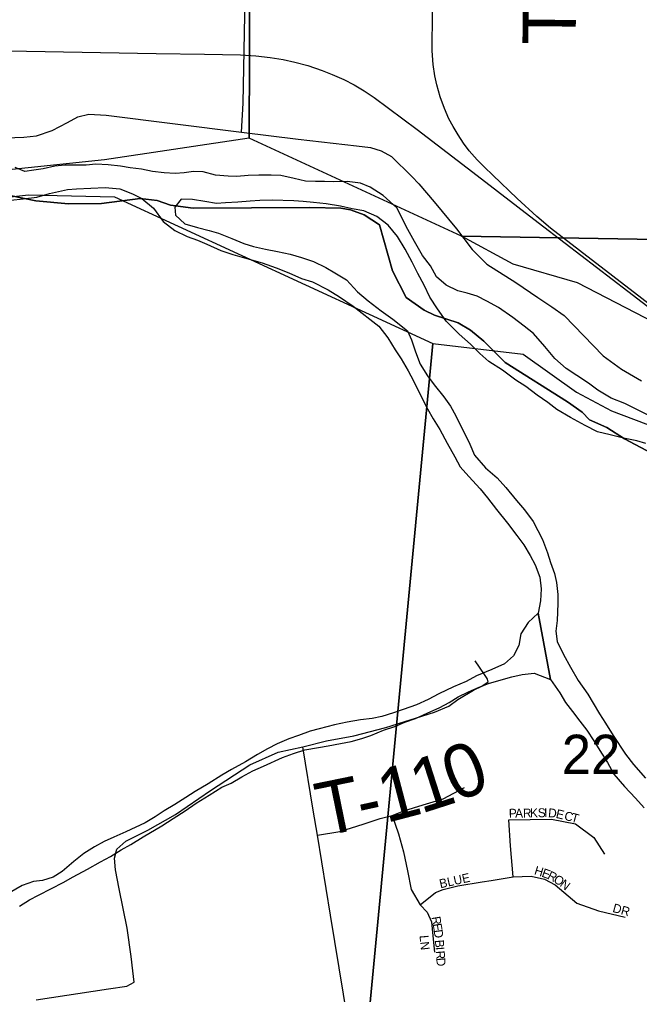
# Model space of a CAD drawing. Extents: x 1310247 to 1552180, y 377264 to 706493.
# Drawn here: x 1398339 to 1401822, y 525062 to 530538 of the extents above; entities that cross this region are included whole.
import ezdxf

# ---------------------------------------------------------------- set-up
doc = ezdxf.new("R2010")
doc.units = 0
for name, color, linetype in [('GM_X_County_Road', 7, 'Continuous'), ('GM_X_Major_River', 7, 'Continuous'), ('GM_X_Minor_River', 7, 'Continuous'), ('GM_X_Rail_Line', 7, 'Continuous'), ('GM_X_Rail_Line_Text', 7, 'Continuous'), ('GM_X_Section', 7, 'Continuous'), ('GM_X_Section_Text', 7, 'Continuous'), ('GM_X_Township', 7, 'Continuous'), ('GM_X_Township_Road', 7, 'Continuous'), ('GM_X_Township_Road_Text', 7, 'Continuous'), ('GM_X_Township_Subdivision', 7, 'Continuous'), ('GM_X_Township_Subdivision_Text', 7, 'Continuous')]:
    doc.layers.add(name, color=color, linetype=linetype)

msp = doc.modelspace()

# ---------------------------------------------------------------- linework, layer by layer
at = {"layer": 'GM_X_County_Road'}
for points in [[(1396748.8, 529601.3), (1396870.4, 529646.6), (1397025.7, 529692.9), (1397319.1, 529747), (1397411.7, 529763.5), (1397653.3, 529831.7), (1397792.9, 529848.2), (1398159.3, 529870.2), (1398362.5, 529877.2), (1398434.7, 529885.8), (1398523.3, 529914.1), (1398608.8, 529960.4), (1398666.1, 529992.5), (1398728.9, 530007.5), (1398825.4, 530000.4), (1399586.3, 529904.7)], [(1399586.3, 529904.7), (1399905, 529866), (1400232, 529828.6), (1400310.6, 529820.2), (1400371.1, 529800.4), (1400428.3, 529768.7), (1400543.8, 529656.9), (1400581.7, 529615.8), (1400668.8, 529513.5), (1400794.3, 529361.9), (1400882.5, 529247.1), (1400964.7, 529164.4), (1401127.6, 529062), (1401250.3, 528976.6), (1401330.1, 528924), (1401399.1, 528875.9), (1401618.7, 528649), (1401721.1, 528574.9), (1401834.2, 528509.3)], [(1398432.7, 525032.2), (1398838.6, 525093.1), (1398941.7, 525109.1), (1398983.9, 525130.9), (1398975.2, 525195), (1398966.4, 525275), (1398943.1, 525433.7), (1398898, 525655), (1398877.6, 525762.7), (1398873.3, 525828.2), (1398884.9, 525877.7), (1398935.9, 525922.8), (1399059.6, 525985.4), (1399215.4, 526072.8), (1399411.9, 526208.2), (1399633.2, 526350.8), (1399791.8, 526422.1), (1399931.6, 526452.7)], [(1400183.5, 524914.8), (1400086.4, 525507.7), (1400013.8, 525957.1), (1399988.2, 526097.8), (1399931.6, 526452.7)]]:
    msp.add_lwpolyline(points, dxfattribs=at)
at = {"layer": 'GM_X_Major_River'}
msp.add_line((1401252.3, 527204.4), (1401321.7, 526830.8), dxfattribs=at)
for points in [[(1399623, 529662.2), (1399560.7, 529656.2), (1399510.7, 529657.7), (1399440.9, 529663.9), (1399371.4, 529682.1), (1399317.4, 529683.8), (1399263.1, 529677.5), (1399212.9, 529673), (1399151, 529676.9), (1399085.2, 529685), (1399023.5, 529697), (1398959.7, 529705), (1398905.9, 529714.7), (1398836.1, 529722.8), (1398768.1, 529725), (1398713.9, 529720.6), (1398651.9, 529720.6), (1398593.8, 529720.4), (1398537.6, 529714.1), (1398471.1, 529700.1), (1398418.8, 529691.7), (1398368.5, 529685.3), (1398315.1, 529707)], [(1401904.9, 528299.3), (1401814.2, 528344.2), (1401739.3, 528380.7), (1401664.1, 528411.1), (1401587.4, 528455.6), (1401536.6, 528495.3), (1401469.9, 528539.5), (1401411.1, 528577.5), (1401346.7, 528633.6), (1401290.8, 528701.6), (1401227, 528773.8), (1401174.2, 528815.5), (1401111.6, 528863.6), (1401029.3, 528920.3), (1400964.4, 528956.5), (1400911.2, 528984.2), (1400853.7, 529002), (1400802, 529013.7), (1400736.9, 529045.8), (1400682.4, 529093.6), (1400648.2, 529154.9), (1400604, 529212.4), (1400558.4, 529292.1), (1400520.5, 529359.5), (1400458.1, 529479.8), (1400382.2, 529550.3), (1400309.6, 529596.7), (1400254.2, 529618.5), (1400180.5, 529628.8), (1400104.4, 529627.2), (1400052.4, 529628.8), (1400002.3, 529628.4), (1399946.3, 529630.1), (1399882.7, 529646.1), (1399807.2, 529662.5), (1399753.2, 529664.2), (1399683.1, 529664.4), (1399623, 529662.2)], [(1398289.4, 529523.2), (1398359.7, 529531.1), (1398436.1, 529540.8), (1398506.8, 529560.6), (1398557.2, 529573.1), (1398607.6, 529583.5), (1398659.8, 529587.9), (1398820.1, 529595), (1398902, 529586.4), (1398973.2, 529560.1), (1399026.4, 529532.4), (1399090.8, 529478.2), (1399146.5, 529404.3), (1399211, 529354.1), (1399280, 529319.9), (1399339.4, 529298), (1399390.8, 529276.3), (1399469.8, 529241.8), (1399537.1, 529217.6), (1399590.7, 529203.9), (1399701.9, 529172.3), (1399781.1, 529143.8), (1399852.3, 529115.5), (1399923.3, 529083.2), (1399984.8, 529065.2), (1400073.5, 529020.3), (1400136.3, 528980.3), (1400212.8, 528927.7), (1400357.4, 528814.9), (1400407.5, 528751.2), (1400449.4, 528683.7), (1400483.9, 528632.4), (1400521.8, 528565.1), (1400552.1, 528507.9), (1400591.7, 528428.5), (1400631.3, 528351), (1400663.6, 528295.9), (1400699.7, 528234.6), (1400741.4, 528159), (1400785.1, 528081.5), (1400815.4, 528026.4), (1400863.7, 527970.7), (1400927.7, 527902.5), (1400968.1, 527851.1), (1401018.1, 527785.4), (1401079.8, 527709.2), (1401133.7, 527639.3), (1401172.1, 527588), (1401208.3, 527526.7), (1401236.7, 527475.7), (1401262.6, 527406.7), (1401270.5, 527340.2), (1401266.4, 527272.2), (1401252.3, 527204.4)], [(1399246.5, 529529.5), (1399211, 529484.6)], [(1401858.4, 528156.3), (1401806.9, 528172), (1401733.2, 528186.3), (1401657.7, 528204.7), (1401586.2, 528223), (1401517.2, 528257.2), (1401434.5, 528301.9), (1401357.9, 528348.4), (1401307, 528386.1), (1401248.3, 528428.1), (1401183.7, 528476.2), (1401126.8, 528512.1), (1401052.4, 528568.6), (1400975.9, 528617.1), (1400925.2, 528662.8), (1400872.8, 528714.6), (1400808.5, 528770.8), (1400736.7, 528843.2), (1400686.8, 528913), (1400644.8, 528978.5), (1400612.8, 529045.7), (1400576.8, 529111), (1400544.8, 529176.2), (1400505, 529247.6), (1400463.1, 529319.1), (1400411.1, 529382.9), (1400346.5, 529431.1), (1400273.4, 529463.4), (1400207.7, 529475.5), (1400142.1, 529489.6), (1400062.4, 529502.1), (1399990.6, 529510.4), (1399932.8, 529516.2), (1399880.8, 529519.8), (1399758.8, 529523.6), (1399688.7, 529521.8), (1399634.5, 529517.4), (1399566.3, 529511.5), (1399496.1, 529507.7), (1399446, 529505.3), (1399380.2, 529515.3), (1399310.5, 529527.5), (1399246.5, 529529.5)], [(1399211, 529484.6), (1399215.7, 529440.2), (1399268.2, 529390.4), (1399339.7, 529370.2), (1399405.2, 529354.1), (1399456.8, 529338.4), (1399531.9, 529308), (1399599.1, 529279.8), (1399652.7, 529264.1), (1399720.2, 529248), (1399787.9, 529235.8), (1399859.5, 529219.6), (1399923, 529201.5), (1399990.4, 529179.4), (1400059.4, 529145.2), (1400110.5, 529115.5), (1400175.3, 529075.3), (1400237.3, 529009.2), (1400297.8, 528957.2), (1400370.2, 528902.8), (1400436.7, 528854.6), (1400518.8, 528789.8), (1400541.2, 528739), (1400563.2, 528672.1), (1400589.1, 528603.1), (1400631.1, 528537.6), (1400669.5, 528486.2), (1400723.5, 528418.4), (1400759.9, 528367.1), (1400790.2, 528312), (1400814.7, 528261.1), (1400844.9, 528204), (1400869.4, 528153), (1400895.5, 528092.1), (1400957.3, 528019.9), (1401023.6, 527963.7), (1401072, 527910), (1401131.8, 527836), (1401176.2, 527784.4), (1401224.2, 527718.8), (1401277.1, 527616.8), (1401304.8, 527541.7), (1401323.2, 527489), (1401345.3, 527426.2), (1401355.7, 527375.7), (1401363.6, 527309.2), (1401364, 527257.1), (1401359.1, 527163), (1401353.2, 527103), (1401359.4, 527044.6), (1401395.2, 526971.3), (1401435, 526899.9), (1401478.7, 526826.3), (1401532.4, 526748.4), (1401562.8, 526697.3), (1401597, 526638.1), (1401631.4, 526584.9), (1401675.3, 526517.3), (1401744.1, 526410.9), (1401788.3, 526353.4), (1401856, 526277.1)], [(1401321.7, 526830.8), (1401374.4, 526755.3), (1401406.8, 526702.2), (1401445.3, 526650.9), (1401487.6, 526597.4), (1401526.1, 526546.1), (1401566.3, 526486.7), (1401598.6, 526431.5), (1401642.5, 526363.9), (1401678.5, 526298.7), (1401738.4, 526230.6), (1401800.4, 526164.5), (1401848.8, 526110.8)]]:
    msp.add_lwpolyline(points, dxfattribs=at)
at = {"layer": 'GM_X_Minor_River'}
msp.add_line((1401321.7, 526830.8), (1401252.3, 527204.4), dxfattribs=at)
for points in [[(1401252.3, 527204.4), (1401196.6, 527152), (1401156.5, 527087.1), (1401144.5, 527021.2), (1401114.7, 526964), (1401063.2, 526919.5), (1400992.2, 526887.6), (1400907, 526852.2), (1400847.9, 526819.9), (1400776.9, 526790), (1400695.6, 526750.4), (1400634.6, 526718.2), (1400569.6, 526688.2), (1400494.7, 526662.4), (1400440.1, 526644.1), (1400375.4, 526624), (1400320.9, 526611.7), (1400254.6, 526603.8), (1400180.2, 526592), (1400109.6, 526576.2), (1400022.9, 526554.8), (1399972.4, 526540.3), (1399905.6, 526516.4), (1399853, 526497.9), (1399786, 526469.9), (1399733.1, 526441.5), (1399676, 526409.2), (1399608.7, 526369.2), (1399529.3, 526325.5), (1399476.2, 526293.1), (1399398.7, 526245.4), (1399325.2, 526201.5), (1399274.2, 526169), (1399210.8, 526128.9), (1399151.7, 526092.7), (1399100.6, 526060.2), (1399045.5, 526025.8), (1398935.8, 525975), (1398868.8, 525945), (1398814, 525920.7), (1398761, 525890.2), (1398699.8, 525854.1), (1398644.3, 525807.7), (1398578.5, 525751.6), (1398527.5, 525721.1), (1398468.8, 525702.8), (1398416.6, 525696.4), (1398353.8, 525674.3), (1398282.5, 525632.4)], [(1398338.2, 525558.5), (1398395.3, 525592.8), (1398446.2, 525619.3), (1398519.5, 525657.2), (1398584.6, 525691.2), (1398639.6, 525721.6), (1398721, 525765.2), (1398794.4, 525807), (1398849.4, 525837.4), (1398910.6, 525873.6), (1398963.6, 525904), (1399033, 525947.9), (1399139, 526008.8), (1399202.4, 526050.9), (1399269.8, 526093), (1399331.2, 526137.2), (1399404.7, 526181), (1399476.1, 526226.9), (1399528.9, 526249.3), (1399588, 526283.6), (1399649.2, 526317.8), (1399710, 526344), (1399815.6, 526392.8), (1399878.4, 526414.9), (1399941.1, 526435), (1400019.6, 526448.6), (1400074, 526459), (1400142.4, 526470.9), (1400202.8, 526483), (1400261.4, 526499.2), (1400312, 526515.7), (1400384.9, 526545.5), (1400447.7, 526567.6), (1400504.5, 526591.9), (1400563.2, 526612.2), (1400630.2, 526642.2), (1400701.3, 526674.1), (1400752.2, 526702.5), (1400803.2, 526733), (1400862.1, 526761.3), (1400921, 526787.5), (1400973.7, 526808), (1401032.3, 526826.2), (1401105, 526846), (1401163.4, 526858.2), (1401229.7, 526866.2), (1401321.7, 526830.8)]]:
    msp.add_lwpolyline(points, dxfattribs=at)
at = {"layer": 'GM_X_Rail_Line'}
for points in [[(1402475.1, 528462.4), (1402399.7, 528531), (1402348.3, 528576.5), (1401322.5, 529366.2), (1401245.8, 529431.9), (1401135.8, 529533.5), (1400998.2, 529664.8), (1400952, 529708.3), (1400909.6, 529750.6), (1400865.4, 529801.2), (1400832.9, 529843.9), (1400802.9, 529889.8), (1400774.8, 529937.7), (1400751.9, 529981.1), (1400726.2, 530038.5), (1400702, 530104.9), (1400683, 530170.6), (1400672.8, 530222.8), (1400663.7, 530285.6), (1400658.1, 530361.6), (1400660.5, 530799.7)], [(1398167.9, 530365.1), (1399106.4, 530347.5), (1399377.5, 530343.4), (1399581.2, 530339.1), (1399666.3, 530334.8), (1399747.5, 530325.9), (1399820.5, 530314.2), (1399885.4, 530299.1), (1399958.1, 530280), (1400039.7, 530252.8), (1400096.4, 530229.9), (1400161.3, 530200.8), (1400219.2, 530170.8), (1400274.7, 530137.8), (1400332.3, 530100.5), (1400572.4, 529920.6), (1400910.1, 529661.8), (1401253.2, 529398), (1401404.3, 529282.6)], [(1401404.3, 529282.6), (1401757.2, 529012.3), (1402475.1, 528462.4)]]:
    msp.add_lwpolyline(points, dxfattribs=at)
at = {"layer": 'GM_X_Section'}
for points in [[(1394300.1, 534734.1), (1399648.2, 534645.7), (1399629, 529871.9), (1398816.2, 529750.5), (1398188.7, 529684.9), (1397894.7, 529685.6), (1397607.8, 529646.2), (1397412.5, 529592.6), (1397227.7, 529556.8), (1397139.3, 529538.9), (1397165.6, 529376.3), (1394220.6, 529425.6)], [(1399648.2, 534645.7), (1404926.4, 534635.9), (1404882.7, 529252.8), (1400822.5, 529320.7), (1399629, 529871.9)], [(1394632.2, 524597.9), (1394515.4, 525784.6), (1394762, 526163), (1394942.5, 526530.9), (1394994.2, 526609.8), (1395048.2, 526782.5), (1395253.1, 527081.9), (1395499.4, 527446.2), (1395844.6, 528022.4), (1395961, 528301.7), (1396143.5, 528763.6), (1396402.2, 528967.7), (1396589.9, 529125.4), (1396689.5, 529197.1), (1397322, 529394.7), (1397692.4, 529500.2), (1397877.8, 529560), (1398019, 529524.7), (1398133.1, 529526.2), (1398389.7, 529554.3), (1398873.5, 529543.2), (1400660.7, 528718.3), (1400210.2, 523974.4)], [(1400822.5, 529320.7), (1404882.7, 529252.8), (1404855.5, 523981.3), (1404604.2, 524056.7), (1404321.4, 524164.5), (1403984.6, 524339.6), (1403701.7, 524595.6), (1403586.6, 524777.3), (1403248.5, 525035), (1403011.3, 525592.4), (1402982.5, 526259.1), (1403005, 526890.6), (1403014.9, 527676.4), (1402881, 528207.5), (1402531, 528465.5), (1401909.4, 528833.8), (1401474.5, 529059.7), (1401112.9, 529164)]]:
    msp.add_lwpolyline(points, close=True, dxfattribs=at)
msp.add_lwpolyline([(1400210.2, 523974.4), (1400660.7, 528718.3), (1401169.3, 528658.7), (1401468.5, 528445.9), (1401666, 528339.3), (1402066.6, 528188.1)], dxfattribs=at)
at = {"layer": 'GM_X_Township'}
for points in [[(1401889.4, 528102.9), (1401738.1, 528183.4), (1401639, 528246.8), (1401542.3, 528289.2), (1401500.3, 528333.4), (1401417.5, 528390.6), (1401067.3, 528612.1), (1400948.6, 528731.1), (1400872.8, 528793.4), (1400802.9, 528833.7), (1400671.2, 528877.3), (1400612.3, 528905.3), (1400510.6, 528976.6), (1400435.4, 529127.4), (1400362.2, 529385.5), (1400274.6, 529441), (1400199.2, 529469.5), (1400143.4, 529478.2), (1399969.4, 529483.1), (1399313.8, 529478.4), (1399186.7, 529495.5), (1399113.2, 529522), (1399017.1, 529532.4), (1398799.7, 529504.8), (1398613.9, 529502.6), (1398431.5, 529520.7), (1398210.1, 529564.9)], [(1398210.1, 529564.9), (1398431.5, 529520.7), (1398613.9, 529502.6), (1398799.7, 529504.8), (1399017.1, 529532.4), (1399113.2, 529522), (1399186.7, 529495.5), (1399313.8, 529478.4), (1399969.4, 529483.1), (1400143.4, 529478.2), (1400199.2, 529469.5), (1400274.6, 529441), (1400362.2, 529385.5), (1400435.4, 529127.4), (1400510.6, 528976.6), (1400612.3, 528905.3), (1400671.2, 528877.3), (1400802.9, 528833.7), (1400872.8, 528793.4), (1400948.6, 528731.1), (1401067.3, 528612.1), (1401417.5, 528390.6), (1401500.3, 528333.4), (1401542.3, 528289.2), (1401639, 528246.8), (1401738.1, 528183.4), (1401889.4, 528102.9)]]:
    msp.add_lwpolyline(points, dxfattribs=at)
at = {"layer": 'GM_X_Township_Road'}
for points in [[(1399586.3, 529904.7), (1399596.2, 530069.2), (1399641.2, 532441.6), (1399654.1, 533920.8), (1399653.8, 534123.5)], [(1399931.6, 526452.7), (1400063, 526486.2), (1400217.8, 526513.8), (1400397.5, 526561.6), (1400671.5, 526647.7), (1400750.2, 526680.7), (1400801.4, 526719.1), (1400890.3, 526771.6), (1400936.7, 526793.8), (1400972.4, 526817.4), (1400967, 526836.2), (1400950.8, 526858.4), (1400899, 526935.2)]]:
    msp.add_lwpolyline(points, dxfattribs=at)
at = {"layer": 'GM_X_Township_Subdivision'}
for points in [[(1400013.8, 525957.1), (1400138.4, 525976.6), (1400269.6, 526018.3), (1400364.5, 526049.3), (1400433.2, 526066.1), (1400499.2, 526093.1), (1400606.9, 526126.7), (1400720, 526160.4), (1400838.4, 526225)], [(1400433.2, 526066.1), (1400467.5, 525964.8), (1400496.6, 525862.1), (1400518.4, 525756.9), (1400539.8, 525652), (1400589.3, 525564.6), (1400629.8, 525523.9), (1400654.4, 525470), (1400661.8, 525390.8), (1400671.3, 525298.4)], [(1401113.3, 525722.3), (1401098.5, 525897.2), (1401088.6, 526043.5), (1401328.8, 526047.3), (1401463.4, 526020.1), (1401565.6, 525943.8), (1401625.1, 525849.3)], [(1400589.3, 525564.6), (1400675.3, 525634.3), (1400719.6, 525652.1), (1400800.9, 525672.8), (1400939, 525694.7), (1400989.7, 525702.7)], [(1400989.7, 525702.7), (1401113.3, 525722.3), (1401213.3, 525726.1), (1401288.1, 525709), (1401348.2, 525677.9), (1401471.1, 525575.1), (1401592.7, 525532.4), (1401742.8, 525496.8)]]:
    msp.add_lwpolyline(points, dxfattribs=at)

# ---------------------------------------------------------------- texts
at = {"layer": 'GM_X_Rail_Line_Text'}
msp.add_text('Transportation, Inc.', height=299, rotation=89.4786, dxfattribs=at).set_placement((1401463.6, 530395))
at = {"layer": 'GM_X_Section_Text'}
msp.add_text('22', height=221, rotation=0, dxfattribs=at).set_placement((1401385.8, 526299.8))
at = {"layer": 'GM_X_Township_Road_Text'}
for s, rotation, p in [('0', 21.5593, (1400789.2, 526139.5)), ('1', 17.8664, (1400593.4, 526075.7)), ('1', 14.7303, (1400397.5, 526023.7)), ('T', 11.568, (1400039.8, 525948.2)), ('-', 12.372, (1400264.1, 525994.1))]:
    msp.add_text(s, height=300, rotation=rotation, dxfattribs=at).set_placement(p)
at = {"layer": 'GM_X_Township_Subdivision_Text'}
for s, rotation, p in [('P', 0.9562, (1401088.6, 526054.3)), ('A', 0.9782, (1401123.8, 526054.8)), ('R', 0.9855, (1401167.8, 526055.6)), ('K', 0.9618, (1401207.4, 526056.3)), ('S', 0.993, (1401251.4, 526057)), ('I', 0.9618, (1401286.6, 526057.6)), ('D', 354.8125, (1401307.2, 526058)), ('E', 347.1897, (1401349.3, 526054.3)), ('C', 346.3082, (1401396.2, 526043.4)), ('T', 344.8503, (1401434.4, 526034.2)), ('BLUE', 12.5243, (1400703.8, 525658)), ('H', 343.0339, (1401227.5, 525737.2)), ('E', 339.9492, (1401269, 525724.6)), ('R', 333.7065, (1401300.7, 525713.1)), ('O', 326.989, (1401334.9, 525696.3)), ('N', 322.1595, (1401370.8, 525673)), ('DR', 344.4724, (1401667.7, 525525.9)), ('R', 279.3905, (1400653.5, 525496.4)), ('E', 279.386, (1400659.9, 525457.3)), ('D', 277.8921, (1400665.6, 525422.9)), ('L', 275.0337, (1400586.3, 525392.5)), ('N', 276.2692, (1400589.5, 525356.3)), ('B', 274.4248, (1400672.8, 525367)), ('I', 274.2881, (1400675.9, 525327.5)), ('R', 274.2898, (1400677.5, 525305.6)), ('D', 274.2881, (1400680.5, 525266.1))]:
    msp.add_text(s, height=50, rotation=rotation, dxfattribs=at).set_placement(p)

doc.saveas('drawing.dxf')
